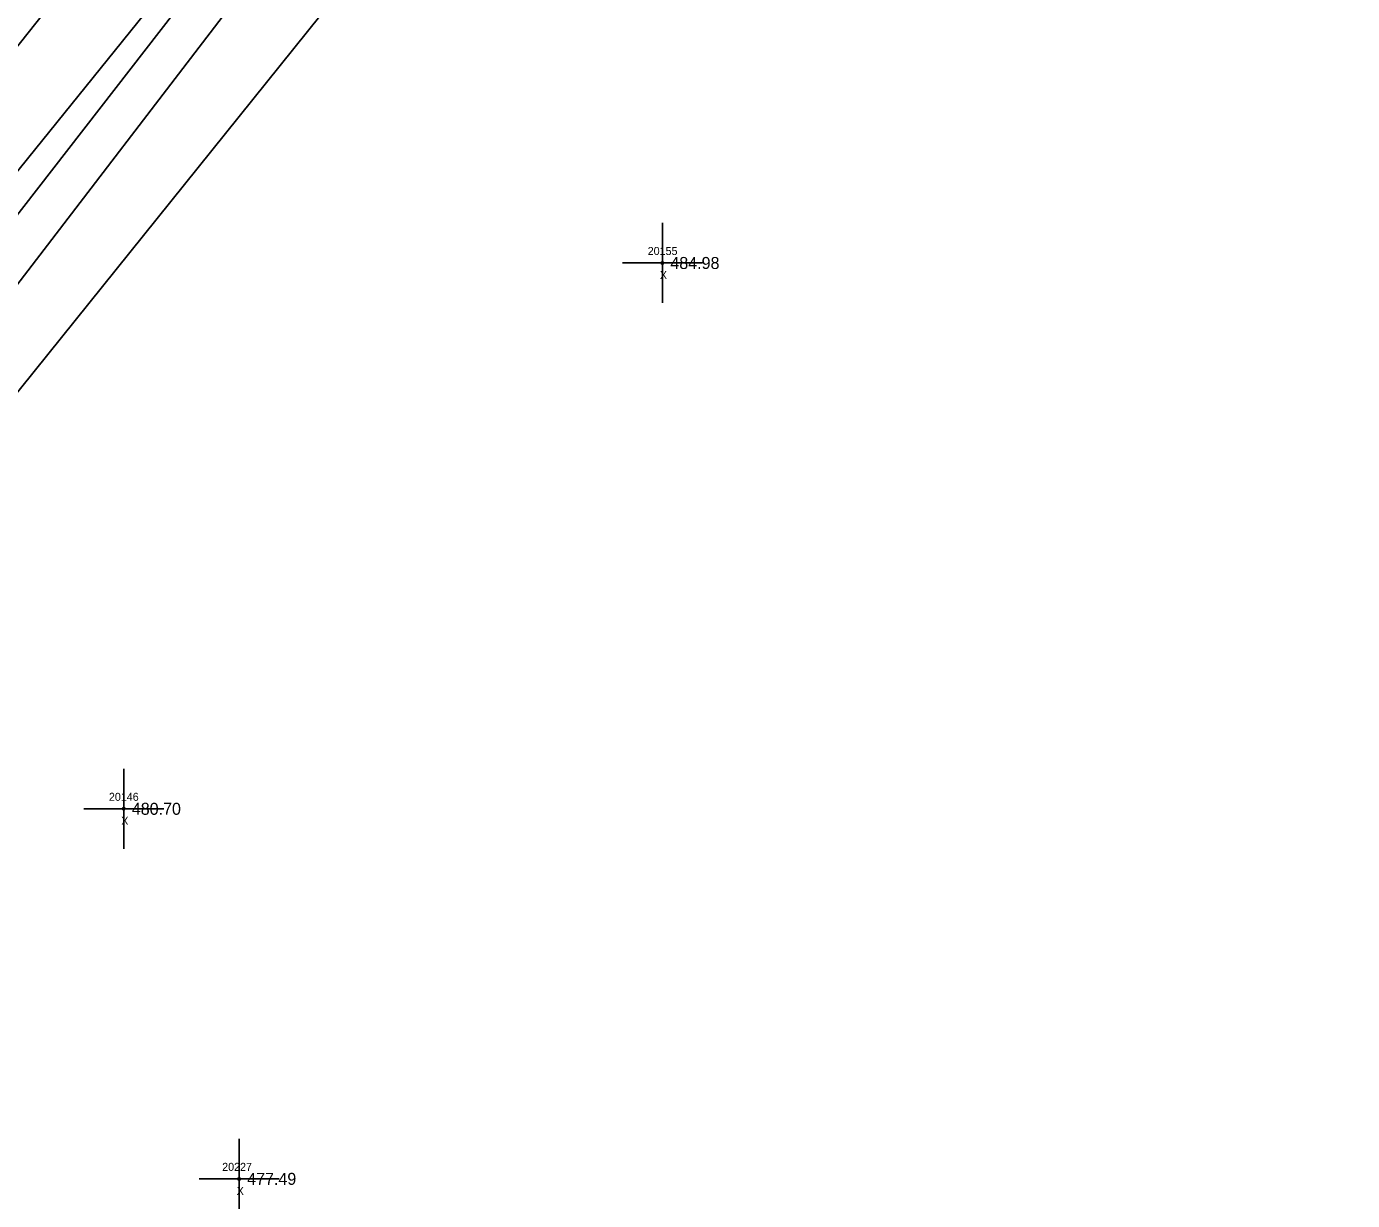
# Model space of a CAD drawing. Extents: x 1789565 to 1790548, y 909019 to 910194.
# Drawn here: x 1790172.5 to 1790338.1, y 909606.8 to 909753.6 of the extents above; entities that cross this region are included whole.
import ezdxf

# ---------------------------------------------------------------- set-up
doc = ezdxf.new("R2010")
doc.units = 0
for name, color, linetype in [('RD_DTM_BkLn1', 7, 'Continuous'), ('RD_DTM_BkLn2', 7, 'Continuous'), ('RD_EX_H2O', 7, 'Continuous'), ('RD_EX_Misc', 7, 'Continuous'), ('RD_EX_Misc_txCode', 7, 'Continuous'), ('RD_EX_Road', 7, 'Continuous'), ('RD_EX_TX_Misc_ELEV', 7, 'Continuous'), ('RD_SMD_Locator', 7, 'Continuous')]:
    doc.layers.add(name, color=color, linetype=linetype)

msp = doc.modelspace()

# ---------------------------------------------------------------- linework, layer by layer
at = {"layer": 'RD_DTM_BkLn1'}
msp.add_lwpolyline([(1790071.24, 909625.67), (1790132.78, 909702.56), (1790193.17, 909778.64), (1790254.11, 909855.13), (1790314.56, 909930.82), (1790375.87, 910006.79), (1790434.17, 910078.51), (1790495.95, 910153.23)], dxfattribs=at)
at = {"layer": 'RD_DTM_BkLn2'}
for points in [[(1790081.67, 909617.32), (1790086.3, 909617), (1790143.13, 909693.7), (1790202.72, 909770.52), (1790263.97, 909846.87), (1790323.52, 909922.76), (1790384.66, 909999.25), (1790423.96, 910046.28)], [(1790092.97, 909612.92), (1790097.34, 909612.95), (1790152.91, 909684.97), (1790214.4, 909761.5), (1790270.76, 909842.42), (1790331.58, 909916.3), (1790391.85, 909993.49), (1790427.85, 910042.91), (1790426.19, 910046.57), (1790423.96, 910046.28)]]:
    msp.add_lwpolyline(points, dxfattribs=at)
at = {"layer": 'RD_EX_H2O'}
msp.add_lwpolyline([(1790092.97, 909612.92), (1790147.38, 909690.09), (1790206.86, 909767.79), (1790266.43, 909845.39), (1790326.38, 909920.19), (1790387.41, 909997.35), (1790424.69, 910044.32)], dxfattribs=at)
at = {"layer": 'RD_EX_Misc'}
for p, q in [((1790251.91, 909719.02), (1790251.91, 909729.02)), ((1790246.91, 909724.02), (1790256.91, 909724.02)), ((1790184.63, 909650.8), (1790184.63, 909660.8)), ((1790179.63, 909655.8), (1790189.63, 909655.8)), ((1790199.04, 909604.55), (1790199.04, 909614.55)), ((1790194.04, 909609.55), (1790204.04, 909609.55))]:
    msp.add_line(p, q, dxfattribs=at)
at = {"layer": 'RD_EX_Road'}
msp.add_lwpolyline([(1790071.25, 909625.72), (1790078.96, 909619.74), (1790139.76, 909696.36), (1790200.89, 909772.13), (1790261.64, 909848.6), (1790322.1, 909924.01), (1790383.38, 910000.26), (1790441.69, 910072.01), (1790503.77, 910147.05)], dxfattribs=at)
at = {"layer": 'RD_SMD_Locator'}
for centre in [(1790251.91, 909724.02), (1790184.63, 909655.8), (1790199.04, 909609.55)]:
    msp.add_circle(centre, 0.15, dxfattribs=at)

# ---------------------------------------------------------------- texts
at = {"layer": 'RD_EX_Misc_txCode'}
for s, p in [('20155', (1790250.08, 909725.02)), ('X', (1790251.6, 909722.02)), ('20146', (1790182.77, 909656.8)), ('X', (1790184.31, 909653.8)), ('20227', (1790196.92, 909610.55)), ('X', (1790198.73, 909607.55))]:
    msp.add_text(s, height=1, dxfattribs=at).set_placement(p)
at = {"layer": 'RD_EX_TX_Misc_ELEV'}
for s, p in [('484.98', (1790252.91, 909723.27)), ('480.70', (1790185.63, 909655.05)), ('477.49', (1790200.04, 909608.8))]:
    msp.add_text(s, height=1.5, dxfattribs=at).set_placement(p)

doc.saveas('drawing.dxf')
